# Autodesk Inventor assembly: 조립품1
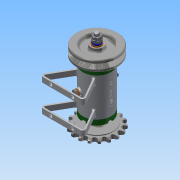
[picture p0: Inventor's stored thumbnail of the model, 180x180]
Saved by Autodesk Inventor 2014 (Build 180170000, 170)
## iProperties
Created: 2016-03
Part Number: 조립품1
Document SubType Name: Assembly
Designer: 406-0014
Author: 406-0014
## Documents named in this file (15)
- C:\Users\406-0014\Desktop\460307V1008\조립품1.iam
- C:\Users\406-0014\Desktop\460307V1008\본체.ipt
- C:\Users\406-0014\Desktop\460307V1008\축.ipt
- C:\Users\406-0014\Desktop\460307V1008\베어링 15 x 32 x 9.ipt
- C:\Users\406-0014\Desktop\460307V1008\커버.ipt
- C:\Users\406-0014\Desktop\460307V1008\오일 실 15 25 7.ipt
- C:\Users\406-0014\Desktop\460307V1008\V벨트풀리.ipt
- C:\Users\406-0014\Desktop\460307V1008\스프로킷.ipt
- C:\Users\406-0014\Desktop\460307V1008\키 3 x 3 x 12.ipt
- C:\Users\406-0014\Desktop\460307V1008\너트 M 8.ipt
- C:\Users\406-0014\Desktop\460307V1008\와셔 8x17.ipt
- C:\Users\406-0014\Desktop\460307V1008\스프링와셔 8.ipt
- C:\Users\406-0014\Desktop\460307V1008\니플 M 6 x 0.75.ipt
- C:\Users\406-0014\Desktop\460307V1008\와셔 6x11.5.ipt
- C:\Users\406-0014\Desktop\460307V1008\볼트 M 6 x 8.ipt
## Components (3 placed, 2 different names)
1. KS B 2023 6002 - 15 x 32 x 9:1
2. KS B 2023 6002 - 15 x 32 x 9:2
3. V벨트풀리:1
## Named parameters: d24_d20 = 0, d25_d21 = 0, d26_d22 = 0
